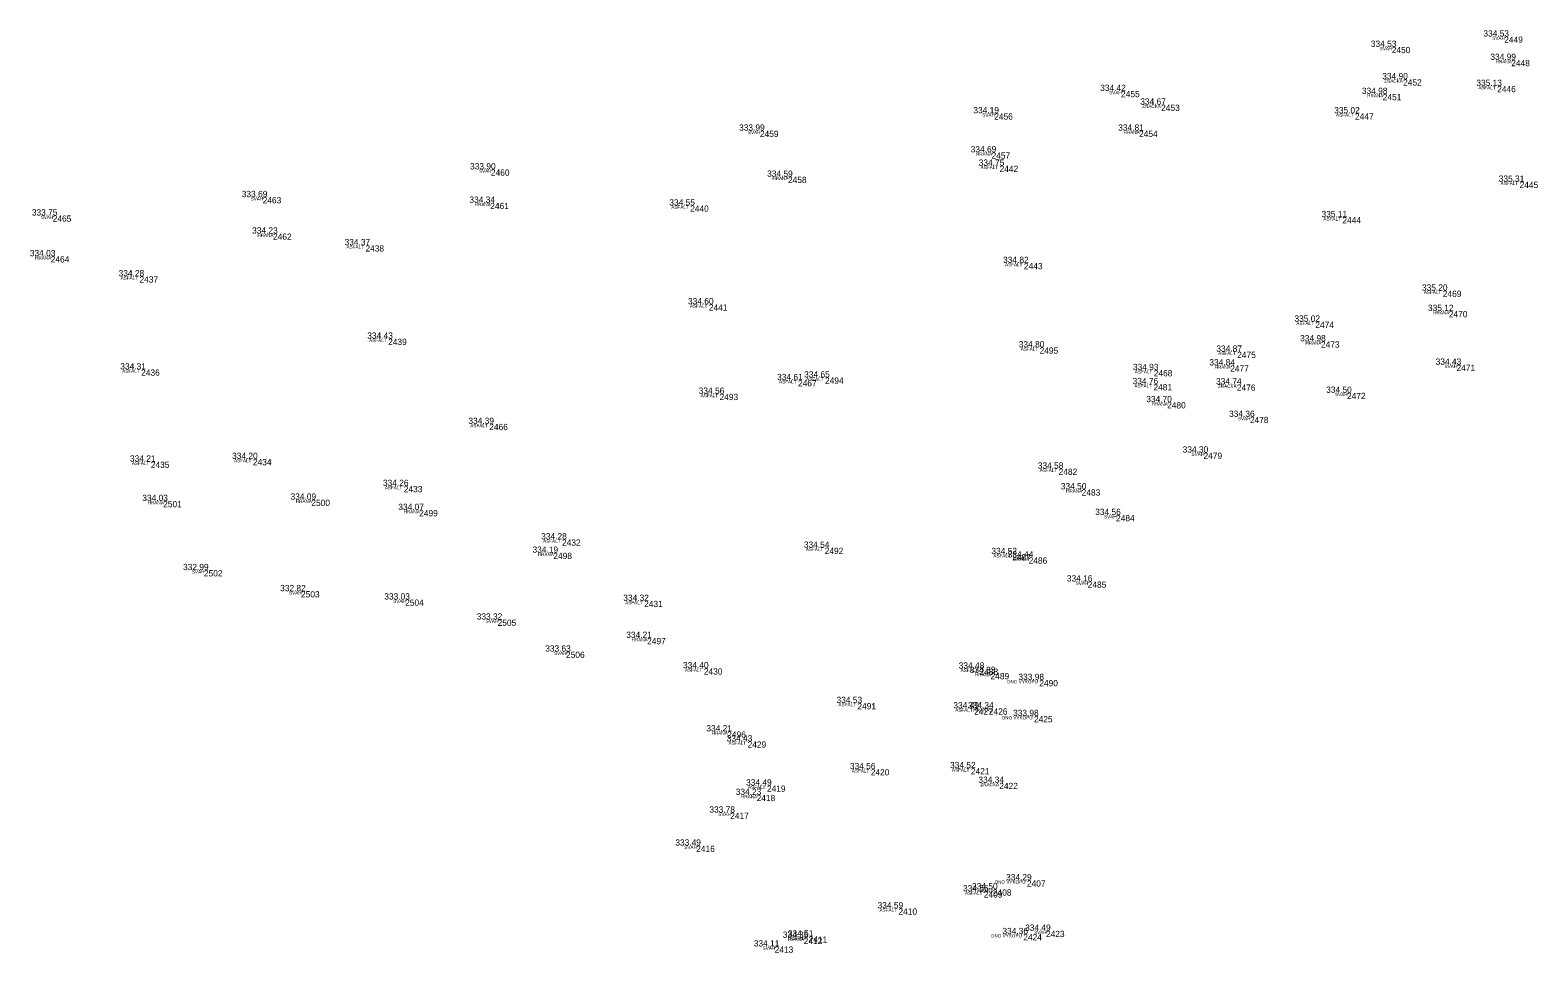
# Model space of a CAD drawing. Extents: x -597865 to -597551, y -1151663 to -1149883.
# Drawn here: x -597692.15 to -597646.97, y -1149910.27 to -1149882.64 of the extents above; entities that cross this region are included whole.
import ezdxf

# ---------------------------------------------------------------- set-up
doc = ezdxf.new("R2010")
doc.units = 0
for name, color, linetype in [('Vrstva 11', 7, 'Continuous'), ('Vrstva 12', 7, 'Continuous'), ('Vrstva 13', 7, 'Continuous'), ('Vrstva 14', 7, 'Continuous')]:
    doc.layers.add(name, color=color, linetype=linetype)

msp = doc.modelspace()

# ---------------------------------------------------------------- linework, layer by layer
at = {"layer": 'Vrstva 11'}
for p, q in [((-597647.98, -1149882.83), (-597647.98, -1149882.83)), ((-597651.35, -1149883.14), (-597651.35, -1149883.14)), ((-597647.77, -1149883.53), (-597647.77, -1149883.53)), ((-597651.01, -1149884.11), (-597651.01, -1149884.11)), ((-597648.19, -1149884.31), (-597648.19, -1149884.31)), ((-597659.46, -1149884.46), (-597659.46, -1149884.46)), ((-597651.62, -1149884.55), (-597651.62, -1149884.55)), ((-597663.26, -1149885.13), (-597663.26, -1149885.13)), ((-597658.26, -1149884.87), (-597658.26, -1149884.87)), ((-597652.45, -1149885.13), (-597652.45, -1149885.13)), ((-597670.28, -1149885.65), (-597670.28, -1149885.65)), ((-597658.92, -1149885.65), (-597658.92, -1149885.65)), ((-597663.34, -1149886.3), (-597663.34, -1149886.3)), ((-597678.34, -1149886.81), (-597678.34, -1149886.81)), ((-597669.44, -1149887.03), (-597669.44, -1149887.03)), ((-597663.1, -1149886.7), (-597663.1, -1149886.7)), ((-597647.52, -1149887.18), (-597647.52, -1149887.18)), ((-597685.18, -1149887.64), (-597685.18, -1149887.64)), ((-597678.36, -1149887.81), (-597678.36, -1149887.81)), ((-597672.37, -1149887.89), (-597672.37, -1149887.89)), ((-597691.47, -1149888.19), (-597691.47, -1149888.19)), ((-597652.83, -1149888.24), (-597652.83, -1149888.24)), ((-597684.87, -1149888.73), (-597684.87, -1149888.73)), ((-597682.1, -1149889.08), (-597682.1, -1149889.08)), ((-597691.53, -1149889.41), (-597691.53, -1149889.41)), ((-597662.37, -1149889.61), (-597662.37, -1149889.61)), ((-597688.87, -1149890.01), (-597688.87, -1149890.01)), ((-597649.82, -1149890.44), (-597649.82, -1149890.44)), ((-597671.81, -1149890.85), (-597671.81, -1149890.85)), ((-597649.64, -1149891.05), (-597649.64, -1149891.05)), ((-597653.64, -1149891.37), (-597653.64, -1149891.37)), ((-597681.42, -1149891.88), (-597681.42, -1149891.88)), ((-597653.47, -1149891.96), (-597653.47, -1149891.96)), ((-597661.9, -1149892.14), (-597661.9, -1149892.14)), ((-597655.98, -1149892.27), (-597655.98, -1149892.27)), ((-597688.82, -1149892.8), (-597688.82, -1149892.8)), ((-597658.48, -1149892.82), (-597658.48, -1149892.82)), ((-597656.19, -1149892.68), (-597656.19, -1149892.68)), ((-597649.41, -1149892.66), (-597649.41, -1149892.66)), ((-597669.14, -1149893.12), (-597669.14, -1149893.12)), ((-597668.33, -1149893.04), (-597668.33, -1149893.04)), ((-597658.49, -1149893.24), (-597658.49, -1149893.24)), ((-597655.99, -1149893.25), (-597655.99, -1149893.25)), ((-597671.49, -1149893.53), (-597671.49, -1149893.53)), ((-597658.08, -1149893.78), (-597658.08, -1149893.78)), ((-597652.69, -1149893.5), (-597652.69, -1149893.5)), ((-597655.6, -1149894.22), (-597655.6, -1149894.22)), ((-597678.39, -1149894.43), (-597678.39, -1149894.43)), ((-597688.53, -1149895.56), (-597688.53, -1149895.56)), ((-597685.47, -1149895.48), (-597685.47, -1149895.48)), ((-597656.99, -1149895.29), (-597656.99, -1149895.29)), ((-597661.33, -1149895.77), (-597661.33, -1149895.77)), ((-597680.95, -1149896.29), (-597680.95, -1149896.29)), ((-597660.64, -1149896.39), (-597660.64, -1149896.39)), ((-597688.16, -1149896.74), (-597688.16, -1149896.74)), ((-597683.72, -1149896.7), (-597683.72, -1149896.7)), ((-597680.49, -1149897.01), (-597680.49, -1149897.01)), ((-597659.61, -1149897.16), (-597659.61, -1149897.16)), ((-597676.21, -1149897.89), (-597676.21, -1149897.89)), ((-597676.47, -1149898.29), (-597676.47, -1149898.29)), ((-597668.34, -1149898.14), (-597668.34, -1149898.14)), ((-597662.72, -1149898.33), (-597662.72, -1149898.33)), ((-597686.94, -1149898.81), (-597686.94, -1149898.81)), ((-597662.23, -1149898.43), (-597662.23, -1149898.43)), ((-597660.46, -1149899.15), (-597660.46, -1149899.15)), ((-597684.03, -1149899.44), (-597684.03, -1149899.44)), ((-597680.91, -1149899.69), (-597680.91, -1149899.69)), ((-597673.75, -1149899.73), (-597673.75, -1149899.73)), ((-597678.14, -1149900.29), (-597678.14, -1149900.29)), ((-597673.66, -1149900.84), (-597673.66, -1149900.84)), ((-597676.09, -1149901.25), (-597676.09, -1149901.25)), ((-597671.96, -1149901.75), (-597671.96, -1149901.75)), ((-597663.7, -1149901.76), (-597663.7, -1149901.76)), ((-597663.37, -1149901.89), (-597663.37, -1149901.89)), ((-597661.91, -1149902.1), (-597661.91, -1149902.1)), ((-597667.36, -1149902.79), (-597667.36, -1149902.79)), ((-597663.86, -1149902.95), (-597663.86, -1149902.95)), ((-597663.42, -1149902.95), (-597663.42, -1149902.95)), ((-597662.07, -1149903.18), (-597662.07, -1149903.18)), ((-597671.26, -1149903.64), (-597671.26, -1149903.64)), ((-597670.65, -1149903.94), (-597670.65, -1149903.94)), ((-597666.96, -1149904.77), (-597666.96, -1149904.77)), ((-597663.96, -1149904.74), (-597663.96, -1149904.74)), ((-597670.38, -1149905.54), (-597670.38, -1149905.54)), ((-597670.07, -1149905.26), (-597670.07, -1149905.26)), ((-597663.11, -1149905.18), (-597663.11, -1149905.18)), ((-597671.17, -1149906.07), (-597671.17, -1149906.07)), ((-597672.19, -1149907.06), (-597672.19, -1149907.06)), ((-597662.28, -1149908.1), (-597662.28, -1149908.1)), ((-597663.57, -1149908.43), (-597663.57, -1149908.43)), ((-597663.3, -1149908.37), (-597663.3, -1149908.37)), ((-597666.13, -1149908.94), (-597666.13, -1149908.94)), ((-597661.71, -1149909.61), (-597661.71, -1149909.61)), ((-597669.84, -1149910.08), (-597669.84, -1149910.08)), ((-597668.97, -1149909.82), (-597668.97, -1149909.82)), ((-597668.82, -1149909.78), (-597668.82, -1149909.78)), ((-597662.39, -1149909.71), (-597662.39, -1149909.71))]:
    msp.add_line(p, q, dxfattribs=at)

# ---------------------------------------------------------------- texts
at = {"layer": 'Vrstva 12'}
for s, p in [('334.53 ', (-597651.975, -1149883.14)), ('334.53 ', (-597648.605, -1149882.83)), ('334.99 ', (-597648.395, -1149883.53)), ('334.90 ', (-597651.635, -1149884.11)), ('334.42 ', (-597660.085, -1149884.46)), ('334.98 ', (-597652.245, -1149884.55)), ('335.13 ', (-597648.815, -1149884.31)), ('334.67 ', (-597658.885, -1149884.87)), ('334.19 ', (-597663.885, -1149885.13)), ('335.02 ', (-597653.075, -1149885.13)), ('333.99 ', (-597670.905, -1149885.65)), ('334.81 ', (-597659.545, -1149885.65)), ('334.69 ', (-597663.965, -1149886.3)), ('333.90 ', (-597678.965, -1149886.81)), ('334.75 ', (-597663.725, -1149886.7)), ('334.59 ', (-597670.065, -1149887.03)), ('335.31 ', (-597648.145, -1149887.18)), ('333.69 ', (-597685.805, -1149887.64)), ('334.34 ', (-597678.985, -1149887.81)), ('334.55 ', (-597672.995, -1149887.89)), ('333.75 ', (-597692.095, -1149888.19)), ('335.11 ', (-597653.455, -1149888.24)), ('334.23 ', (-597685.495, -1149888.73)), ('334.37 ', (-597682.725, -1149889.08)), ('334.03 ', (-597692.155, -1149889.41)), ('334.82 ', (-597662.995, -1149889.61)), ('334.28 ', (-597689.495, -1149890.01)), ('335.20 ', (-597650.445, -1149890.44)), ('334.60 ', (-597672.435, -1149890.85)), ('335.12 ', (-597650.265, -1149891.05)), ('335.02 ', (-597654.265, -1149891.37)), ('334.43 ', (-597682.045, -1149891.88)), ('334.80 ', (-597662.525, -1149892.14)), ('334.98 ', (-597654.095, -1149891.96)), ('334.84 ', (-597656.815, -1149892.68)), ('334.87 ', (-597656.605, -1149892.27)), ('334.43 ', (-597650.035, -1149892.66)), ('334.31 ', (-597689.445, -1149892.8)), ('334.61 ', (-597669.765, -1149893.12)), ('334.65 ', (-597668.955, -1149893.04)), ('334.93 ', (-597659.105, -1149892.82)), ('334.56 ', (-597672.115, -1149893.53)), ('334.76 ', (-597659.115, -1149893.24)), ('334.74 ', (-597656.615, -1149893.25)), ('334.50 ', (-597653.315, -1149893.5)), ('334.70 ', (-597658.705, -1149893.78)), ('334.39 ', (-597679.015, -1149894.43)), ('334.36 ', (-597656.225, -1149894.22)), ('334.30 ', (-597657.615, -1149895.29)), ('334.21 ', (-597689.155, -1149895.56)), ('334.20 ', (-597686.095, -1149895.48)), ('334.58 ', (-597661.955, -1149895.77)), ('334.26 ', (-597681.575, -1149896.29)), ('334.03 ', (-597688.785, -1149896.74)), ('334.09 ', (-597684.345, -1149896.7)), ('334.50 ', (-597661.265, -1149896.39)), ('334.07 ', (-597681.115, -1149897.01)), ('334.56 ', (-597660.235, -1149897.16)), ('334.28 ', (-597676.835, -1149897.89)), ('334.19 ', (-597677.095, -1149898.29)), ('334.54 ', (-597668.965, -1149898.14)), ('334.52 ', (-597663.345, -1149898.33)), ('334.44 ', (-597662.855, -1149898.43)), ('332.99 ', (-597687.565, -1149898.81)), ('332.82 ', (-597684.655, -1149899.44)), ('334.16 ', (-597661.085, -1149899.15)), ('333.03 ', (-597681.535, -1149899.69)), ('334.32 ', (-597674.375, -1149899.73)), ('333.32 ', (-597678.765, -1149900.29)), ('333.63 ', (-597676.715, -1149901.25)), ('334.21 ', (-597674.285, -1149900.84)), ('334.40 ', (-597672.585, -1149901.75)), ('334.48 ', (-597664.325, -1149901.76)), ('334.33 ', (-597663.995, -1149901.89)), ('333.98 ', (-597662.535, -1149902.1)), ('334.53 ', (-597667.985, -1149902.79)), ('334.49 ', (-597664.485, -1149902.95)), ('334.34 ', (-597664.045, -1149902.95)), ('333.98 ', (-597662.695, -1149903.18)), ('334.21 ', (-597671.885, -1149903.64)), ('334.43 ', (-597671.275, -1149903.94)), ('334.56 ', (-597667.585, -1149904.77)), ('334.52 ', (-597664.585, -1149904.74)), ('334.49 ', (-597670.695, -1149905.26)), ('334.34 ', (-597663.735, -1149905.18)), ('334.23 ', (-597671.005, -1149905.54)), ('333.78 ', (-597671.795, -1149906.07)), ('333.49 ', (-597672.815, -1149907.06)), ('334.56 ', (-597664.195, -1149908.43)), ('334.50 ', (-597663.925, -1149908.37)), ('334.29 ', (-597662.905, -1149908.1)), ('334.59 ', (-597666.755, -1149908.94)), ('334.35 ', (-597669.595, -1149909.82)), ('334.51 ', (-597669.445, -1149909.78)), ('334.36 ', (-597663.015, -1149909.71)), ('334.49 ', (-597662.335, -1149909.61)), ('334.11 ', (-597670.465, -1149910.08))]:
    msp.add_text(s, height=0.1875, dxfattribs=at).set_placement(p)
at = {"layer": 'Vrstva 13'}
for s, p in [('2449', (-597647.98, -1149883.018)), ('2450', (-597651.35, -1149883.328)), ('2448', (-597647.77, -1149883.718)), ('2452', (-597651.01, -1149884.298)), ('2446', (-597648.19, -1149884.498)), ('2455', (-597659.46, -1149884.647)), ('2451', (-597651.62, -1149884.738)), ('2456', (-597663.26, -1149885.318)), ('2453', (-597658.26, -1149885.058)), ('2447', (-597652.45, -1149885.318)), ('2459', (-597670.28, -1149885.838)), ('2454', (-597658.92, -1149885.838)), ('2457', (-597663.34, -1149886.488)), ('2460', (-597678.34, -1149886.998)), ('2458', (-597669.44, -1149887.218)), ('2442', (-597663.1, -1149886.887)), ('2445', (-597647.52, -1149887.367)), ('2463', (-597685.18, -1149887.828)), ('2461', (-597678.36, -1149887.998)), ('2440', (-597672.37, -1149888.078)), ('2465', (-597691.47, -1149888.377)), ('2444', (-597652.83, -1149888.427)), ('2462', (-597684.87, -1149888.917)), ('2438', (-597682.1, -1149889.268)), ('2464', (-597691.53, -1149889.597)), ('2443', (-597662.37, -1149889.798)), ('2437', (-597688.87, -1149890.198)), ('2469', (-597649.82, -1149890.627)), ('2441', (-597671.81, -1149891.038)), ('2470', (-597649.64, -1149891.238)), ('2474', (-597653.64, -1149891.558)), ('2439', (-597681.42, -1149892.068)), ('2473', (-597653.47, -1149892.147)), ('2495', (-597661.9, -1149892.328)), ('2475', (-597655.98, -1149892.458)), ('2436', (-597688.82, -1149892.988)), ('2468', (-597658.48, -1149893.008)), ('2477', (-597656.19, -1149892.867)), ('2471', (-597649.41, -1149892.847)), ('2467', (-597669.14, -1149893.308)), ('2494', (-597668.33, -1149893.228)), ('2481', (-597658.49, -1149893.427)), ('2476', (-597655.99, -1149893.438)), ('2493', (-597671.49, -1149893.718)), ('2480', (-597658.08, -1149893.968)), ('2472', (-597652.69, -1149893.688)), ('2478', (-597655.6, -1149894.407)), ('2466', (-597678.39, -1149894.617)), ('2435', (-597688.53, -1149895.748)), ('2434', (-597685.47, -1149895.667)), ('2479', (-597656.99, -1149895.478)), ('2482', (-597661.33, -1149895.958)), ('2433', (-597680.95, -1149896.478)), ('2483', (-597660.64, -1149896.578)), ('2501', (-597688.16, -1149896.927)), ('2500', (-597683.72, -1149896.887)), ('2499', (-597680.49, -1149897.198)), ('2484', (-597659.61, -1149897.347)), ('2432', (-597676.21, -1149898.078)), ('2498', (-597676.47, -1149898.478)), ('2492', (-597668.34, -1149898.328)), ('2487', (-597662.72, -1149898.518)), ('2502', (-597686.94, -1149898.998)), ('2486', (-597662.23, -1149898.617)), ('2485', (-597660.46, -1149899.338)), ('2503', (-597684.03, -1149899.627)), ('2504', (-597680.91, -1149899.877)), ('2431', (-597673.75, -1149899.917)), ('2505', (-597678.14, -1149900.478)), ('2497', (-597673.66, -1149901.028)), ('2506', (-597676.09, -1149901.438)), ('2430', (-597671.96, -1149901.938)), ('2488', (-597663.7, -1149901.948)), ('2489', (-597663.37, -1149902.078)), ('2490', (-597661.91, -1149902.288)), ('2491', (-597667.36, -1149902.978)), ('2427', (-597663.86, -1149903.137)), ('2426', (-597663.42, -1149903.137)), ('2425', (-597662.07, -1149903.367)), ('2496', (-597671.26, -1149903.828)), ('2429', (-597670.65, -1149904.127)), ('2420', (-597666.96, -1149904.958)), ('2421', (-597663.96, -1149904.927)), ('2418', (-597670.38, -1149905.728)), ('2419', (-597670.07, -1149905.448)), ('2422', (-597663.11, -1149905.367)), ('2417', (-597671.17, -1149906.258)), ('2416', (-597672.19, -1149907.248)), ('2407', (-597662.28, -1149908.288)), ('2409', (-597663.57, -1149908.617)), ('2408', (-597663.3, -1149908.558)), ('2410', (-597666.13, -1149909.127)), ('2423', (-597661.71, -1149909.798)), ('2413', (-597669.84, -1149910.268)), ('2412', (-597668.97, -1149910.008)), ('2411', (-597668.82, -1149909.968)), ('2424', (-597662.39, -1149909.897))]:
    msp.add_text(s, height=0.1875, dxfattribs=at).set_placement(p)
at = {"layer": 'Vrstva 14'}
for s, p in [('SVAH', (-597648.338, -1149882.93)), ('SVAH', (-597651.708, -1149883.24)), ('HRANA', (-597648.237, -1149883.63)), ('ZNACKA', (-597651.577, -1149884.21)), ('ASFALT', (-597648.757, -1149884.41)), ('SVAH', (-597659.818, -1149884.56)), ('HRANA', (-597652.087, -1149884.65)), ('SVAH', (-597663.618, -1149885.23)), ('ZNACKA', (-597658.827, -1149884.97)), ('ASFALT', (-597653.017, -1149885.23)), ('SVAH', (-597670.638, -1149885.75)), ('HRANA', (-597659.387, -1149885.75)), ('HRANA', (-597663.807, -1149886.4)), ('SVAH', (-597678.698, -1149886.91)), ('HRANA', (-597669.907, -1149887.13)), ('ASFALT', (-597663.667, -1149886.8)), ('ASFALT', (-597648.087, -1149887.28)), ('SVAH', (-597685.538, -1149887.74)), ('HRANA', (-597678.827, -1149887.91)), ('ASFALT', (-597672.937, -1149887.99)), ('SVAH', (-597691.828, -1149888.29)), ('ASFALT', (-597653.397, -1149888.34)), ('HRANA', (-597685.337, -1149888.83)), ('ASFALT', (-597682.667, -1149889.18)), ('HRANA', (-597691.997, -1149889.51)), ('ASFALT', (-597662.937, -1149889.71)), ('ASFALT', (-597689.437, -1149890.11)), ('ASFALT', (-597650.387, -1149890.54)), ('ASFALT', (-597672.377, -1149890.95)), ('HRANA', (-597650.107, -1149891.15)), ('ASFALT', (-597654.207, -1149891.47)), ('ASFALT', (-597681.987, -1149891.98)), ('HRANA', (-597653.937, -1149892.06)), ('ASFALT', (-597662.467, -1149892.24)), ('ASFALT', (-597656.547, -1149892.37)), ('ASFALT', (-597689.387, -1149892.9)), ('ASFALT', (-597659.047, -1149892.92)), ('HRANA', (-597656.657, -1149892.78)), ('SVAH', (-597649.768, -1149892.76)), ('ASFALT', (-597669.707, -1149893.22)), ('ASFALT', (-597668.897, -1149893.14)), ('ASFALT', (-597659.057, -1149893.34)), ('ZNACKA', (-597656.557, -1149893.35)), ('ASFALT', (-597672.057, -1149893.63)), ('HRANA', (-597658.547, -1149893.88)), ('SVAH', (-597653.048, -1149893.6)), ('SVAH', (-597655.958, -1149894.32)), ('ASFALT', (-597678.957, -1149894.53)), ('ASFALT', (-597689.097, -1149895.66)), ('ASFALT', (-597686.037, -1149895.58)), ('SVAH', (-597657.348, -1149895.39)), ('ASFALT', (-597661.897, -1149895.87)), ('ASFALT', (-597681.517, -1149896.39)), ('HRANA', (-597661.107, -1149896.49)), ('HRANA', (-597688.627, -1149896.84)), ('HRANA', (-597684.187, -1149896.8)), ('HRANA', (-597680.957, -1149897.11)), ('SVAH', (-597659.968, -1149897.26)), ('ASFALT', (-597676.777, -1149897.99)), ('HRANA', (-597676.937, -1149898.39)), ('ASFALT', (-597668.907, -1149898.24)), ('ASFALT', (-597663.287, -1149898.43)), ('SVAH', (-597687.298, -1149898.91)), ('HRANA', (-597662.697, -1149898.53)), ('SVAH', (-597660.818, -1149899.25)), ('SVAH', (-597684.388, -1149899.54)), ('SVAH', (-597681.268, -1149899.79)), ('ASFALT', (-597674.317, -1149899.83)), ('SVAH', (-597678.498, -1149900.39)), ('HRANA', (-597674.127, -1149900.94)), ('SVAH', (-597676.448, -1149901.35)), ('ASFALT', (-597672.527, -1149901.85)), ('ASFALT', (-597664.267, -1149901.86)), ('HRANA', (-597663.837, -1149901.99)), ('DNO VYKOPU', (-597662.873, -1149902.2)), ('ASFALT', (-597667.927, -1149902.89)), ('ASFALT', (-597664.427, -1149903.05)), ('HRANA', (-597663.887, -1149903.05)), ('DNO VYKOPU', (-597663.032, -1149903.28)), ('HRANA', (-597671.727, -1149903.74)), ('ASFALT', (-597671.217, -1149904.04)), ('ASFALT', (-597667.527, -1149904.87)), ('ASFALT', (-597664.527, -1149904.84)), ('HRANA', (-597670.847, -1149905.64)), ('ASFALT', (-597670.637, -1149905.36)), ('ZNACKA', (-597663.677, -1149905.28)), ('SVAH', (-597671.528, -1149906.17)), ('SVAH', (-597672.548, -1149907.16)), ('DNO VYKOPU', (-597663.243, -1149908.2)), ('ASFALT', (-597664.137, -1149908.53)), ('HRANA', (-597663.767, -1149908.47)), ('ASFALT', (-597666.697, -1149909.04)), ('SVAH', (-597662.068, -1149909.71)), ('SVAH', (-597670.198, -1149910.18)), ('HRANA', (-597669.437, -1149909.92)), ('ASFALT', (-597669.387, -1149909.88)), ('DNO VYKOPU', (-597663.353, -1149909.81))]:
    msp.add_text(s, height=0.1, dxfattribs=at).set_placement(p)

doc.saveas('drawing.dxf')
